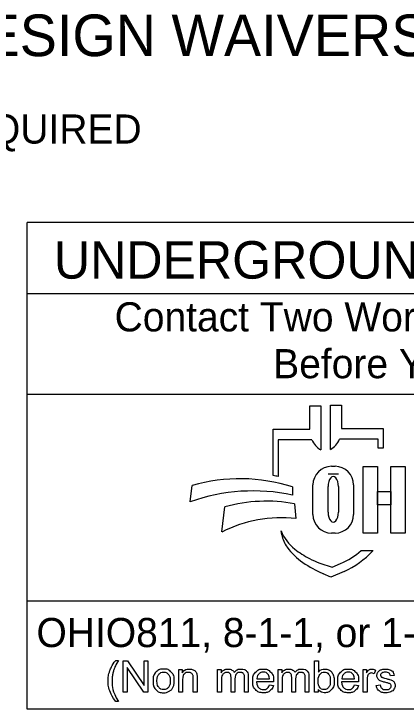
# Model space of a CAD drawing. Extents: x -7.5 to 53.5, y 0 to 22.
# Drawn here: x 2.962 to 4.845, y 2.146 to 5.486 of the extents above; entities that cross this region are included whole.
import ezdxf

# ---------------------------------------------------------------- set-up
doc = ezdxf.new("R2010")
doc.units = 0
doc.layers.add('SH_Data', color=7, linetype='Continuous')
doc.layers.add('SH_Text', color=7, linetype='Continuous')

msp = doc.modelspace()

# ---------------------------------------------------------------- linework, layer by layer
at = {"layer": 'SH_Data'}
for p, q in [((3.026, 2.1465), (3.026, 4.484)), ((7.276, 4.484), (3.026, 4.484)), ((3.026, 4.1424), (7.276, 4.1424)), ((3.026, 3.659), (7.276, 3.659)), ((7.276, 2.6643), (3.026, 2.6643)), ((7.276, 2.1465), (3.026, 2.1465))]:
    msp.add_line(p, q, dxfattribs=at)
at = {"layer": 'SH_Text'}
for p, q in [((4.3821, 3.492), (4.3821, 3.6035)), ((4.3821, 3.6035), (4.4357, 3.6035)), ((4.4357, 3.6035), (4.4357, 3.3914)), ((4.4814, 3.3937), (4.4814, 3.6058)), ((4.4814, 3.6058), (4.535, 3.6058)), ((4.535, 3.6058), (4.535, 3.4943)), ((4.2061, 3.2681), (4.2061, 3.492)), ((4.2061, 3.492), (4.3821, 3.492)), ((4.535, 3.4943), (4.7343, 3.4943)), ((4.7343, 3.4943), (4.7343, 3.4005)), ((4.2314, 3.4405), (4.2314, 3.2637)), ((4.3925, 3.4405), (4.2314, 3.4405)), ((4.711, 3.4429), (4.5246, 3.4429)), ((4.711, 3.4005), (4.711, 3.4429)), ((4.7343, 3.4005), (4.711, 3.4005)), ((4.4871, 3.3128), (4.5036, 3.3128)), ((4.5203, 3.2758), (4.4705, 3.2758)), ((3.8088, 3.1418), (3.8181, 3.2199)), ((4.2994, 3.2134), (4.2994, 3.1746)), ((4.3976, 3.0813), (4.3976, 3.2233)), ((4.4705, 3.0927), (4.4705, 3.2151)), ((4.5203, 3.2151), (4.5203, 3.0927)), ((4.5931, 3.2233), (4.5931, 3.0813)), ((3.9606, 2.9973), (3.9753, 3.1174)), ((4.3094, 3.1328), (4.3156, 3.0619)), ((4.2483, 2.9844), (4.2452, 3.0023)), ((4.5036, 2.9918), (4.4871, 2.9918)), ((4.6286, 2.9085), (4.686, 2.9085)), ((4.4301, 2.8481), (4.4896, 2.8276)), ((4.4896, 2.8276), (4.5306, 2.8454)), ((4.5468, 2.8081), (4.4835, 2.7806)), ((4.4835, 2.7806), (4.4462, 2.797))]:
    msp.add_line(p, q, dxfattribs=at)
for points in [[(4.6395, 3.3118), (4.7075, 3.3118), (4.7075, 2.9918), (4.6395, 2.9918)], [(4.7716, 3.3118), (4.8396, 3.3118), (4.8396, 2.9918), (4.7716, 2.9918)], [(4.7075, 3.1919), (4.7716, 3.1919), (4.7716, 3.1279), (4.7075, 3.1279)]]:
    msp.add_lwpolyline(points, close=True, dxfattribs=at)
for points in [[(3.4507, 2.3803), (3.4638, 2.3803)], [(3.4874, 2.2276), (3.4874, 2.3778), (3.5077, 2.3778), (3.5867, 2.2598), (3.5867, 2.3778), (3.6057, 2.3778), (3.6057, 2.2276), (3.5854, 2.2276), (3.5064, 2.3455), (3.5064, 2.2276), (3.4874, 2.2276)], [(4.4229, 2.2276), (4.4058, 2.2276), (4.4058, 2.3778), (4.4242, 2.3778), (4.4242, 2.3243)], [(3.7534, 2.2276), (3.7534, 2.3364), (3.77, 2.3364), (3.77, 2.321)], [(3.9398, 2.2276), (3.9398, 2.3364), (3.9563, 2.3364), (3.9563, 2.3211)], [(4.2311, 2.2276), (4.2311, 2.3364), (4.2476, 2.3364), (4.2476, 2.3211)], [(4.6389, 2.2276), (4.6389, 2.3364), (4.6555, 2.3364), (4.6555, 2.32)], [(4.698, 2.333), (4.6915, 2.3159)], [(4.7879, 2.3083), (4.7699, 2.3059)], [(3.7718, 2.287), (3.7718, 2.2276), (3.7534, 2.2276)], [(3.8417, 2.2945), (3.8417, 2.2276), (3.8233, 2.2276), (3.8233, 2.2938)], [(3.9582, 2.284), (3.9582, 2.2276), (3.9398, 2.2276)], [(4.0229, 2.2908), (4.0229, 2.2276), (4.0044, 2.2276), (4.0044, 2.2983)], [(4.0873, 2.3023), (4.0873, 2.2276), (4.0689, 2.2276), (4.0689, 2.2961)], [(4.2085, 2.2773), (4.1274, 2.2773)], [(4.1284, 2.2924), (4.1892, 2.2924)], [(4.2496, 2.284), (4.2496, 2.2276), (4.2311, 2.2276)], [(4.3142, 2.2908), (4.3142, 2.2276), (4.2958, 2.2276), (4.2958, 2.2983)], [(4.3787, 2.3023), (4.3787, 2.2276), (4.3602, 2.2276), (4.3602, 2.2961)], [(4.6165, 2.2773), (4.5354, 2.2773)], [(4.5364, 2.2924), (4.5972, 2.2924)], [(4.6574, 2.2846), (4.6574, 2.2276), (4.6389, 2.2276)], [(4.189, 2.2627), (4.208, 2.2603)], [(4.4229, 2.2412), (4.4229, 2.2276)], [(4.597, 2.2627), (4.616, 2.2603)], [(4.7015, 2.2601), (4.7197, 2.263)], [(3.4638, 2.1834), (3.4507, 2.1834)]]:
    msp.add_lwpolyline(points, dxfattribs=at)
for centre, radius, start, end in [((4.4838, 3.4773), 0.0985, 201.9296, 240.7469), ((4.4333, 3.4796), 0.0985, 299.2531, 338.0704), ((4.4871, 3.2233), 0.0895, 90, 180), ((4.5036, 3.2233), 0.0895, 0, 90), ((4.0482, 2.4338), 0.8191, 72.1402, 106.3144), ((4.078, 2.4591), 0.8191, 79.2074, 81.0007), ((4.1113, 2.3027), 0.8919, 77.8238, 109.8274), ((4.1752, 2.4131), 0.7322, 79.44, 105.8467), ((4.4871, 3.0813), 0.0895, 180, 270), ((4.5036, 3.0813), 0.0895, 270, 0), ((4.2472, 2.4298), 0.6357, 83.8248, 116.8021), ((4.4326, 3.0744), 0.2008, 201.0457, 232.5314), ((4.3896, 3.0085), 0.1433, 189.6817, 216.0884), ((4.5232, 3.1059), 0.3088, 216.0884, 235.7167), ((4.6251, 3.3256), 0.5173, 232.5314, 241.794), ((4.3872, 3.1759), 0.3602, 293.4582, 312.0712), ((4.3872, 3.1759), 0.401, 293.4582, 317.8286), ((4.6898, 3.3502), 0.6044, 235.7167, 246.2325), ((4.54, 3.1668), 0.3371, 241.794, 250.9821)]:
    msp.add_arc(centre, radius, start, end, dxfattribs=at)
for centre, start_param, end_param in [((4.4954, 3.2151), 4.712389, 7.853982), ((4.4954, 3.0927), 1.570796, 4.712389)]:
    msp.add_ellipse(centre, major_axis=(0, 0.0484), ratio=0.514403, start_param=start_param, end_param=end_param, dxfattribs=at)
for points in [[(3.4507, 2.1834), (3.4354, 2.2027), (3.4248, 2.2285), (3.4143, 2.2543), (3.4143, 2.282), (3.4143, 2.3063), (3.4222, 2.3287), (3.4314, 2.3546), (3.4507, 2.3803)], [(3.4638, 2.3803), (3.4515, 2.359), (3.4475, 2.3499), (3.4412, 2.3357), (3.4377, 2.3204), (3.4333, 2.3012), (3.4333, 2.2819), (3.4333, 2.2326), (3.4638, 2.1834)], [(3.6299, 2.282), (3.6299, 2.3122), (3.6467, 2.3268), (3.6607, 2.3389), (3.6809, 2.3389), (3.7033, 2.3389), (3.7175, 2.3242), (3.7317, 2.3095), (3.7317, 2.2836), (3.7317, 2.2626), (3.7254, 2.2505), (3.7191, 2.2385), (3.7071, 2.2319), (3.6951, 2.2252), (3.6809, 2.2252), (3.658, 2.2252), (3.644, 2.2398), (3.6299, 2.2545), (3.6299, 2.282)], [(3.77, 2.321), (3.7819, 2.3389), (3.8046, 2.3389), (3.8144, 2.3389), (3.8226, 2.3353), (3.8309, 2.3318), (3.835, 2.326), (3.8391, 2.3203), (3.8407, 2.3124), (3.8417, 2.3073), (3.8417, 2.2945)], [(3.9563, 2.3211), (3.9614, 2.3291), (3.9699, 2.334), (3.9784, 2.3389), (3.9893, 2.3389), (4.0013, 2.3389), (4.0091, 2.3338), (4.0168, 2.3288), (4.02, 2.3198), (4.0329, 2.3389), (4.0536, 2.3389), (4.0699, 2.3389), (4.0786, 2.3299), (4.0873, 2.3209), (4.0873, 2.3023)], [(4.208, 2.2603), (4.2035, 2.2436), (4.1913, 2.2344), (4.1791, 2.2252), (4.1602, 2.2252), (4.1363, 2.2252), (4.1223, 2.2399), (4.1084, 2.2546), (4.1084, 2.2811), (4.1084, 2.3085), (4.1225, 2.3237), (4.1366, 2.3389), (4.1592, 2.3389), (4.181, 2.3389), (4.1948, 2.324), (4.2086, 2.3091), (4.2086, 2.2822), (4.2086, 2.2806), (4.2085, 2.2773)], [(4.2476, 2.3211), (4.2528, 2.3291), (4.2613, 2.334), (4.2698, 2.3389), (4.2806, 2.3389), (4.2927, 2.3389), (4.3005, 2.3338), (4.3082, 2.3288), (4.3114, 2.3198), (4.3243, 2.3389), (4.345, 2.3389), (4.3612, 2.3389), (4.3699, 2.3299), (4.3787, 2.3209), (4.3787, 2.3023)], [(4.4242, 2.3243), (4.4359, 2.3389), (4.454, 2.3389), (4.4641, 2.3389), (4.473, 2.3348), (4.482, 2.3308), (4.4878, 2.3234), (4.4936, 2.3161), (4.4968, 2.3058), (4.5001, 2.2954), (4.5001, 2.2837), (4.5001, 2.2557), (4.4863, 2.2405), (4.4724, 2.2252), (4.4531, 2.2252), (4.4338, 2.2252), (4.4229, 2.2412)], [(4.616, 2.2603), (4.6115, 2.2436), (4.5993, 2.2344), (4.5871, 2.2252), (4.5682, 2.2252), (4.5443, 2.2252), (4.5303, 2.2399), (4.5164, 2.2546), (4.5164, 2.2811), (4.5164, 2.3085), (4.5305, 2.3237), (4.5446, 2.3389), (4.5672, 2.3389), (4.589, 2.3389), (4.6028, 2.324), (4.6166, 2.3091), (4.6166, 2.2822), (4.6166, 2.2806), (4.6165, 2.2773)], [(4.6555, 2.32), (4.6619, 2.3315), (4.6672, 2.3352), (4.6726, 2.3389), (4.6791, 2.3389), (4.6884, 2.3389), (4.698, 2.333)], [(4.7197, 2.263), (4.7213, 2.252), (4.7283, 2.2462), (4.7353, 2.2403), (4.748, 2.2403), (4.7607, 2.2403), (4.7669, 2.2455), (4.7731, 2.2507), (4.7731, 2.2577), (4.7731, 2.2639), (4.7676, 2.2675), (4.7638, 2.27), (4.7487, 2.2738), (4.7284, 2.2789), (4.7206, 2.2826), (4.7127, 2.2863), (4.7087, 2.2929), (4.7046, 2.2996), (4.7046, 2.3075), (4.7046, 2.3148), (4.708, 2.321), (4.7113, 2.3272), (4.717, 2.3313), (4.7213, 2.3345), (4.7288, 2.3367), (4.7362, 2.3389), (4.7447, 2.3389), (4.7576, 2.3389), (4.7673, 2.3352), (4.777, 2.3315), (4.7816, 2.3252), (4.7862, 2.3189), (4.7879, 2.3083)], [(3.6489, 2.282), (3.6489, 2.2611), (3.658, 2.2507), (3.6671, 2.2403), (3.6809, 2.2403), (3.6946, 2.2403), (3.7036, 2.2508), (3.7127, 2.2612), (3.7127, 2.2826), (3.7127, 2.3028), (3.7036, 2.3132), (3.6944, 2.3236), (3.6809, 2.3236), (3.6671, 2.3236), (3.658, 2.3133), (3.6489, 2.3029), (3.6489, 2.282)], [(3.8233, 2.2938), (3.8233, 2.305), (3.8211, 2.3106), (3.819, 2.3162), (3.8135, 2.3195), (3.808, 2.3228), (3.8007, 2.3228), (3.7889, 2.3228), (3.7803, 2.3154), (3.7718, 2.3079), (3.7718, 2.287)], [(4.0044, 2.2983), (4.0044, 2.3105), (3.9999, 2.3167), (3.9954, 2.3228), (3.9852, 2.3228), (3.9774, 2.3228), (3.9708, 2.3187), (3.9641, 2.3146), (3.9612, 2.3068), (3.9582, 2.2989), (3.9582, 2.284)], [(4.0689, 2.2961), (4.0689, 2.3072), (4.0671, 2.312), (4.0653, 2.3169), (4.0606, 2.3199), (4.0559, 2.3228), (4.0495, 2.3228), (4.038, 2.3228), (4.0304, 2.3152), (4.0229, 2.3076), (4.0229, 2.2908)], [(4.1892, 2.2924), (4.1879, 2.3062), (4.1822, 2.3131), (4.1734, 2.3237), (4.1593, 2.3237), (4.1466, 2.3237), (4.138, 2.3152), (4.1293, 2.3067), (4.1284, 2.2924)], [(4.2958, 2.2983), (4.2958, 2.3105), (4.2913, 2.3167), (4.2868, 2.3228), (4.2765, 2.3228), (4.2687, 2.3228), (4.2621, 2.3187), (4.2555, 2.3146), (4.2525, 2.3068), (4.2496, 2.2989), (4.2496, 2.284)], [(4.3602, 2.2961), (4.3602, 2.3072), (4.3584, 2.312), (4.3567, 2.3169), (4.3519, 2.3199), (4.3472, 2.3228), (4.3409, 2.3228), (4.3294, 2.3228), (4.3218, 2.3152), (4.3142, 2.3076), (4.3142, 2.2908)], [(4.4226, 2.2829), (4.4226, 2.2633), (4.4279, 2.2546), (4.4366, 2.2403), (4.4515, 2.2403), (4.4635, 2.2403), (4.4723, 2.2508), (4.4811, 2.2613), (4.4811, 2.2821), (4.4811, 2.3035), (4.4727, 2.3136), (4.4642, 2.3237), (4.4523, 2.3237), (4.4402, 2.3237), (4.4314, 2.3132), (4.4226, 2.3027), (4.4226, 2.2829)], [(4.5972, 2.2924), (4.5959, 2.3062), (4.5902, 2.3131), (4.5814, 2.3237), (4.5673, 2.3237), (4.5546, 2.3237), (4.546, 2.3152), (4.5373, 2.3067), (4.5364, 2.2924)], [(4.6915, 2.3159), (4.6848, 2.3199), (4.6781, 2.3199), (4.6721, 2.3199), (4.6673, 2.3162), (4.6625, 2.3126), (4.6604, 2.3061), (4.6574, 2.2963), (4.6574, 2.2846)], [(4.7699, 2.3059), (4.7686, 2.3143), (4.7627, 2.319), (4.7568, 2.3237), (4.7461, 2.3237), (4.7333, 2.3237), (4.7279, 2.3195), (4.7225, 2.3153), (4.7225, 2.3097), (4.7225, 2.3061), (4.7247, 2.3032), (4.727, 2.3002), (4.7318, 2.2983), (4.7346, 2.2973), (4.7481, 2.2936), (4.7677, 2.2884), (4.7755, 2.285), (4.7832, 2.2817), (4.7876, 2.2754), (4.7921, 2.269), (4.7921, 2.2596), (4.7921, 2.2504), (4.7867, 2.2422), (4.7813, 2.2341), (4.7711, 2.2297), (4.761, 2.2252), (4.7481, 2.2252), (4.7269, 2.2252), (4.7157, 2.234), (4.7046, 2.2428), (4.7015, 2.2601)], [(4.1274, 2.2773), (4.1284, 2.2594), (4.1375, 2.2498), (4.1466, 2.2403), (4.1603, 2.2403), (4.1704, 2.2403), (4.1776, 2.2457), (4.1848, 2.251), (4.189, 2.2627)], [(4.5354, 2.2773), (4.5364, 2.2594), (4.5455, 2.2498), (4.5546, 2.2403), (4.5683, 2.2403), (4.5784, 2.2403), (4.5856, 2.2457), (4.5928, 2.251), (4.597, 2.2627)]]:
    msp.add_open_spline(points, degree=3, dxfattribs=at)

# ---------------------------------------------------------------- texts
for s, height, p in [('ADA DESIGN WAIVERS', 0.2, (1.9944, 5.2831)), ('NONE REQUIRED ', 0.14, (1.9944, 4.8631)), ('UNDERGROUND UTILITIES', 0.18, (3.1542, 4.2143)), ('Contact Two Working Days', 0.14, (3.4457, 3.9608)), ('Before You Dig', 0.14, (4.2069, 3.7358)), ('OHIO811, 8-1-1, or 1-800-362-2764', 0.14, (3.0705, 2.4443))]:
    msp.add_text(s, height=height, dxfattribs=at).set_placement(p)

doc.saveas('drawing.dxf')
